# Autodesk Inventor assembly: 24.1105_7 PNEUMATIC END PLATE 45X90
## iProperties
Created: 2007-06
Part Number: 24.1105_7 PNEUMATIC END PLATE 45X90
Document SubType Name: Assembly
Designer: Andy Moles
Author: Andy Moles
